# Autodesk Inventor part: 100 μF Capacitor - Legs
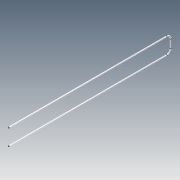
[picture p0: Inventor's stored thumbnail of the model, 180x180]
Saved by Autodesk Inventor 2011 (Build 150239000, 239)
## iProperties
Created: 2013-02
Part Number: 100 μF Capacitor - Legs
Material: Steel, Mild
Document SubType Name: Modeling
Designer: Lance
Mass: 0.154331 g
Surface Area: 1.57472 cm^2
Volume: 0.019635 cm^3
Density: 7.86 g/cm^3
Author: Lance
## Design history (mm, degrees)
sketch "Sketch1"
  geometry: C1 r 0.25 at (0, 0); 1 further point
  constraints: 1 centre point, 1 coincident
  dimensions: "d0" = 0.5 diameter of C1
sketch "Sketch2"
  geometry: L1 (-45, 2)-(-1, 2); L2 (0, 1)-(0, -1); L3 (-1, -2)-(-48, -2); A1 r 1 centre (-1, 1) between (0, 1) and (-1, 2); A2 r 1 centre (-1, -1) between (-1, -2) and (0, -1); 2 further points
  constraints: 6 end point, 4 point on circle, 4 tangent, 2 centre point, 1 coincident, 1 equal radius, 1 horizontal, 1 midpoint, 1 parallel, 1 perpendicular
  dimensions: "d3" = 1 radius of A1; "d4" = 4 distance between parallel lines of L3 L1; "d5" = 45 distance from line of L2 L1.start; "d7" = 3 horizontal distance of L3.end L1.start
sweep "Sweep1" sketch "Sketch1", "Sketch2" dims "d6" = 0
body "Solid2"
